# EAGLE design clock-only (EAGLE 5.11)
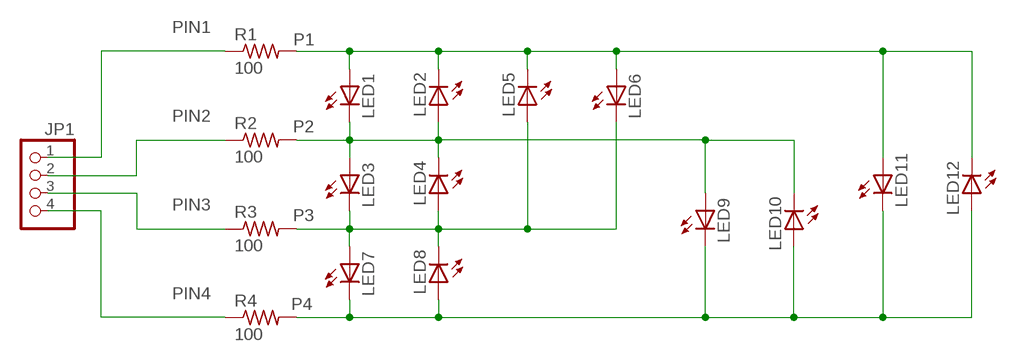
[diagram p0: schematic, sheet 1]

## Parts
JP1  PINHD-1X4  [1X04]
LED1  LEDCHIPLED_0805  [CHIPLED_0805]
LED2  LEDCHIPLED_0805  [CHIPLED_0805]
LED3  LEDCHIPLED_0805  [CHIPLED_0805]
LED4  LEDCHIPLED_0805  [CHIPLED_0805]
LED5  LEDCHIPLED_0805  [CHIPLED_0805]
LED6  LEDCHIPLED_0805  [CHIPLED_0805]
LED7  LEDCHIPLED_0805  [CHIPLED_0805]
LED8  LEDCHIPLED_0805  [CHIPLED_0805]
LED9  LEDCHIPLED_0805  [CHIPLED_0805]
LED10  LEDCHIPLED_0805  [CHIPLED_0805]
LED11  LEDCHIPLED_0805  [CHIPLED_0805]
LED12  LEDCHIPLED_0805  [CHIPLED_0805]
R1  100  R-US_R0805  [R0805]
R2  100  R-US_R0805  [R0805]
R3  100  R-US_R0805  [R0805]
R4  100  R-US_R0805  [R0805]

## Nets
P1: LED1.A LED2.C LED5.C LED6.A LED11.A LED12.C R1.2
P2: LED1.C LED2.A LED3.A LED4.C LED9.A LED10.C R2.2
P3: LED3.C LED4.A LED5.A LED6.C LED7.A LED8.C R3.2
P4: LED7.C LED8.A LED9.C LED10.A LED11.C LED12.A R4.2
PIN1: JP1.1 R1.1
PIN2: JP1.2 R2.1
PIN3: JP1.3 R3.1
PIN4: JP1.4 R4.1

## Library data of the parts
JP1 = pinhead:PINHD-1X4: PIN HEADER
LED1-LED12 = led:LED: LED
R1-R4 = resistor:R-US_: RESISTOR, American symbol

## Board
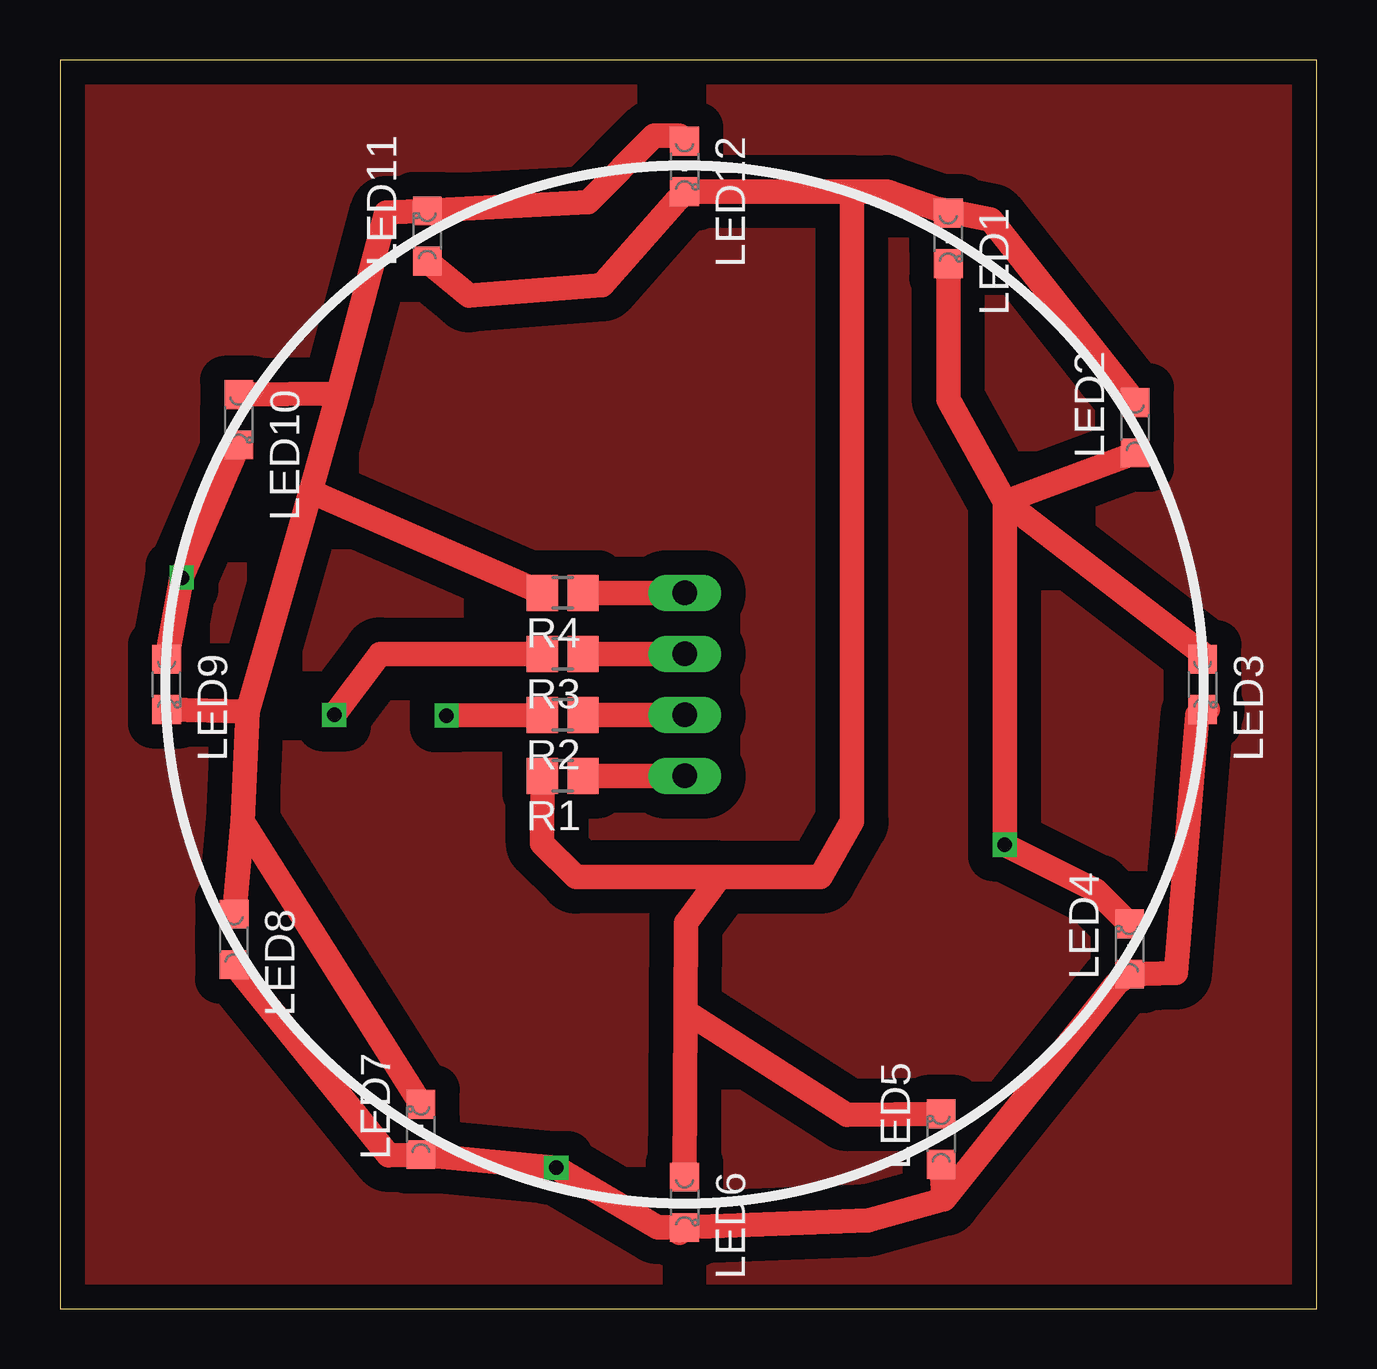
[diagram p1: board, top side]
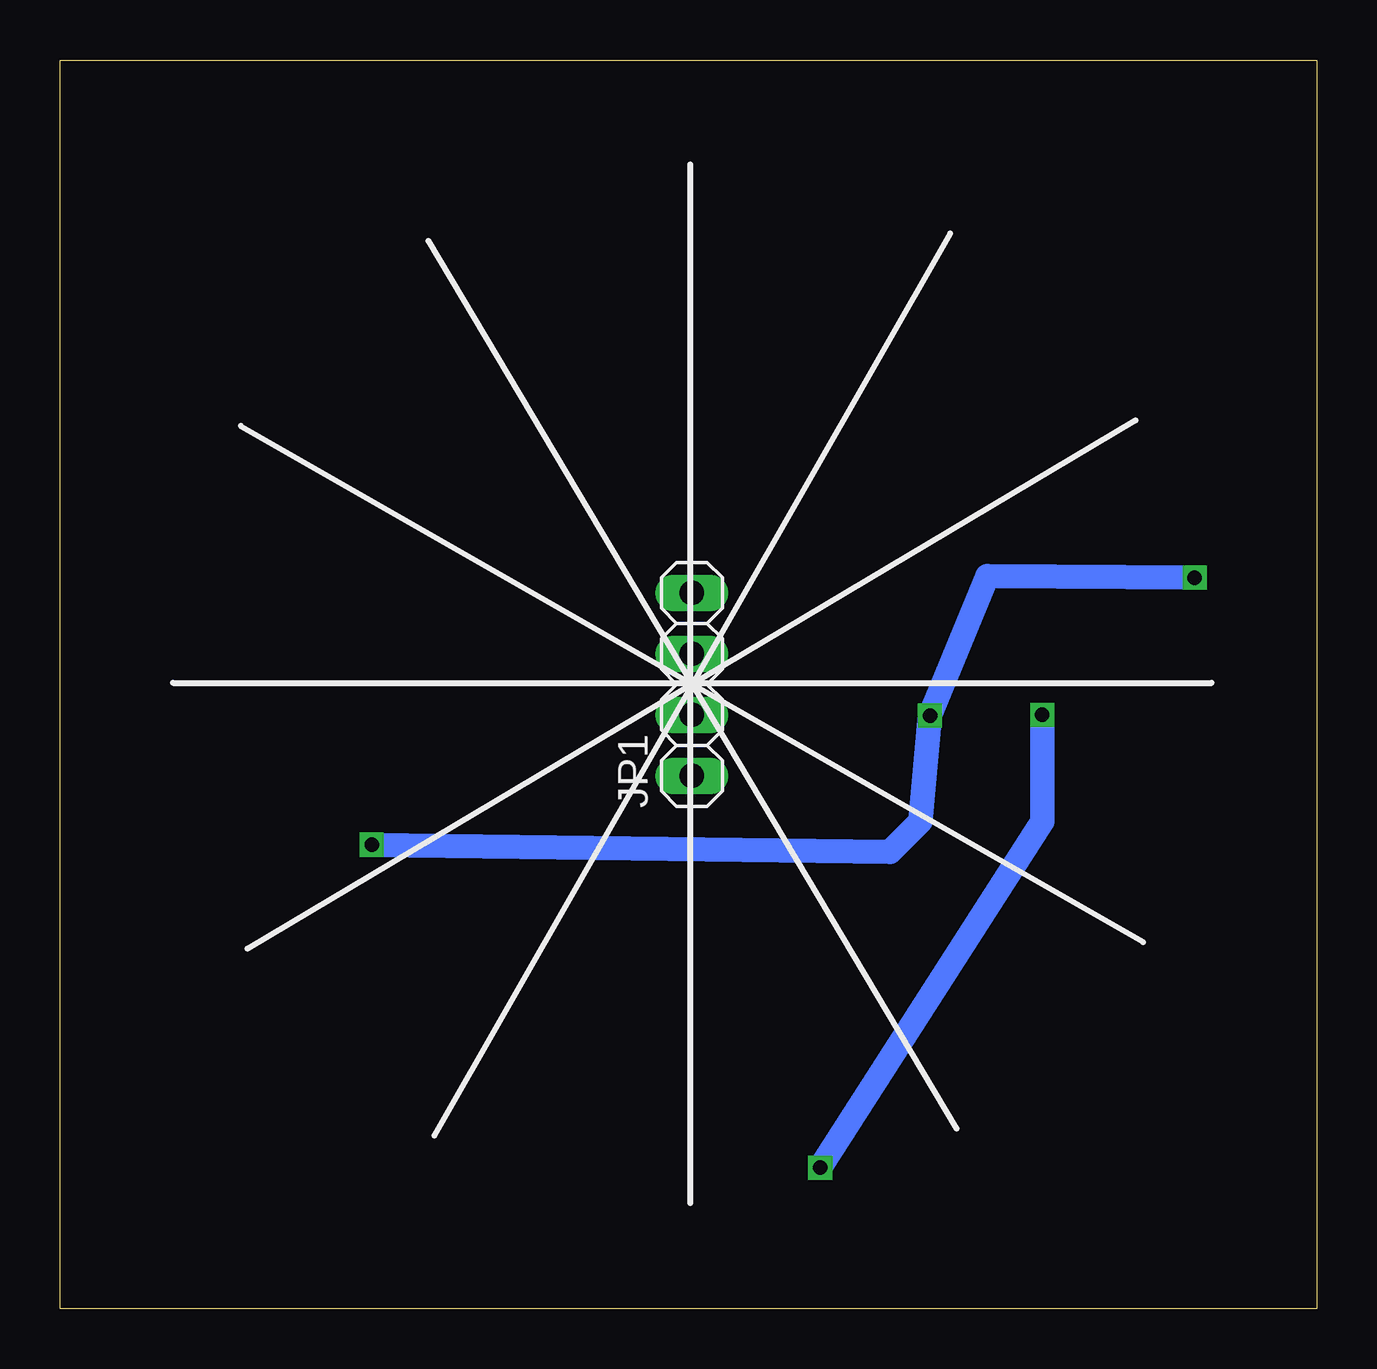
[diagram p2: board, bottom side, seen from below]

Size 52.38 x 52.06 mm. Coordinates in mm from the lower left corner, seen from the top.
Outline: 0,0 52.38,0 52.38,52.06 0,52.06 0,0
Copper layers (1*16): Top 0.035mm / dielectric 1.5mm / Bottom 0.035mm
Design rules "default": minimum track width 10mil, minimum drill 0.6mm, track to track 8mil, track to pad 8mil, pad to pad 8mil, via to via 8mil, smd to smd 8mil, copper to edge 40mil, drill to drill 8mil, minimum pad ring 10mil, minimum via ring 8mil, stop-mask expansion 4mil, vias tented up to drill 0mil, thermal gap 10mil

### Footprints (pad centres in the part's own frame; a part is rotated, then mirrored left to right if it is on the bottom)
1X04 = drill 1.016 long: 1 -3.81,0; 2 -1.27,0; 3 1.27,0; 4 3.81,0
CHIPLED_0805 = smd 1.2 x 1.2: A 0,-1.05; C 0,1.05
R0805 = smd 1.3 x 1.5: 1 -0.85,0; 2 0.85,0

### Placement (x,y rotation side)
JP1  26.04,26.04 90 bottom
LED1  37.02,44.62 180 top
LED2  44.81,36.73 0 top
LED3  47.62,26.04 180 top
LED4  44.58,15.01 0 top
LED5  36.73,7.08 0 top
LED6  26.04,4.45 180 top
LED7  15.04,7.49 0 top
LED8  7.25,15.4 180 top
LED9  4.45,26.04 180 top
LED10  7.46,37.06 180 top
LED11  15.31,44.72 0 top
LED12  26.04,47.62 180 top
R1  20.95,22.23 180 top
R2  20.95,24.77 180 top
R3  20.95,27.3 180 top
R4  20.95,29.84 180 top

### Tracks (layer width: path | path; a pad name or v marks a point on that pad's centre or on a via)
N$1
  pour Top (isolate 1.016, no thermals): 0,52.07 52.07,52.07 52.07,0 0,0 0,1.27
P1
  Top 1.016: LED11.A 17.05,42.23 22.6,42.69 LED12.C 33.02,46.58 | 33.02,46.58 34.48,46.58 36.51,45.85 | 36.51,45.85 LED1.A | 33.02,46.58 33.02,20.32 31.7,18 27.5,18 | R1.2 20.1,19.4 21.5,18 27.5,18 | LED6.A 26.08,12.4 | 26.08,12.4 26.1,16.1 27.5,18 | LED5.C 32.8,8.1 26.08,12.4 | LED2.C 38.8,45.4 36.51,45.85
P2  (via drill 0.6)
  Top 1.016: LED3.A 47.62,27.3 39.38,33.65 | 39.38,33.65 LED2.A | 39.38,33.65 v39.38,19.35 43.18,17.45 LED4.C | LED1.C 37.02,37.91 39.38,33.65 | LED9.A v5.08,30.48 LED10.C | v16.11,24.73 R2.2
  Bottom 1.016: v5.08,30.48 13.72,30.54 v16.11,24.73 16.51,20.32 17.78,19.05 v39.38,19.35
P3  (via drill 0.6)
  Top 1.016: 47.84,24.98 LED3.C 47.41,24.77 46.5,14 LED4.A 44.03,13.55 36.85,4.56 | LED6.C 25.82,3.17 | R3.2 13.34,27.3 v11.43,24.77 | LED6.C 24.9,3.4 v20.69,5.89 LED7.A 13.7,6.4 LED8.C | LED6.C 33.7,3.7 36.85,4.56 | 36.85,4.56 LED5.A
  Bottom 1.016: v11.43,24.77 11.43,20.32 v20.69,5.89
P4
  Top 1.016: LED12.A 25.82,48.9 24.77,48.9 22,46.13 LED11.C 13.6,45.7 11.6,38.15 | 7.62,20.32 7.83,24.9 | LED8.A 7.62,20.32 | 7.62,20.32 LED7.C | 7.83,24.9 LED9.C | 7.83,24.9 10.45,34.07 | 10.45,34.07 11.6,38.15 | 10.45,34.07 R4.2 | 11.6,38.15 LED10.A
PIN1
  Top 1.016: R1.1 JP1.1
PIN2
  Top 1.016: R2.1 JP1.2
PIN3
  Top 1.016: R3.1 JP1.3
PIN4
  Top 1.016: R4.1 JP1.4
